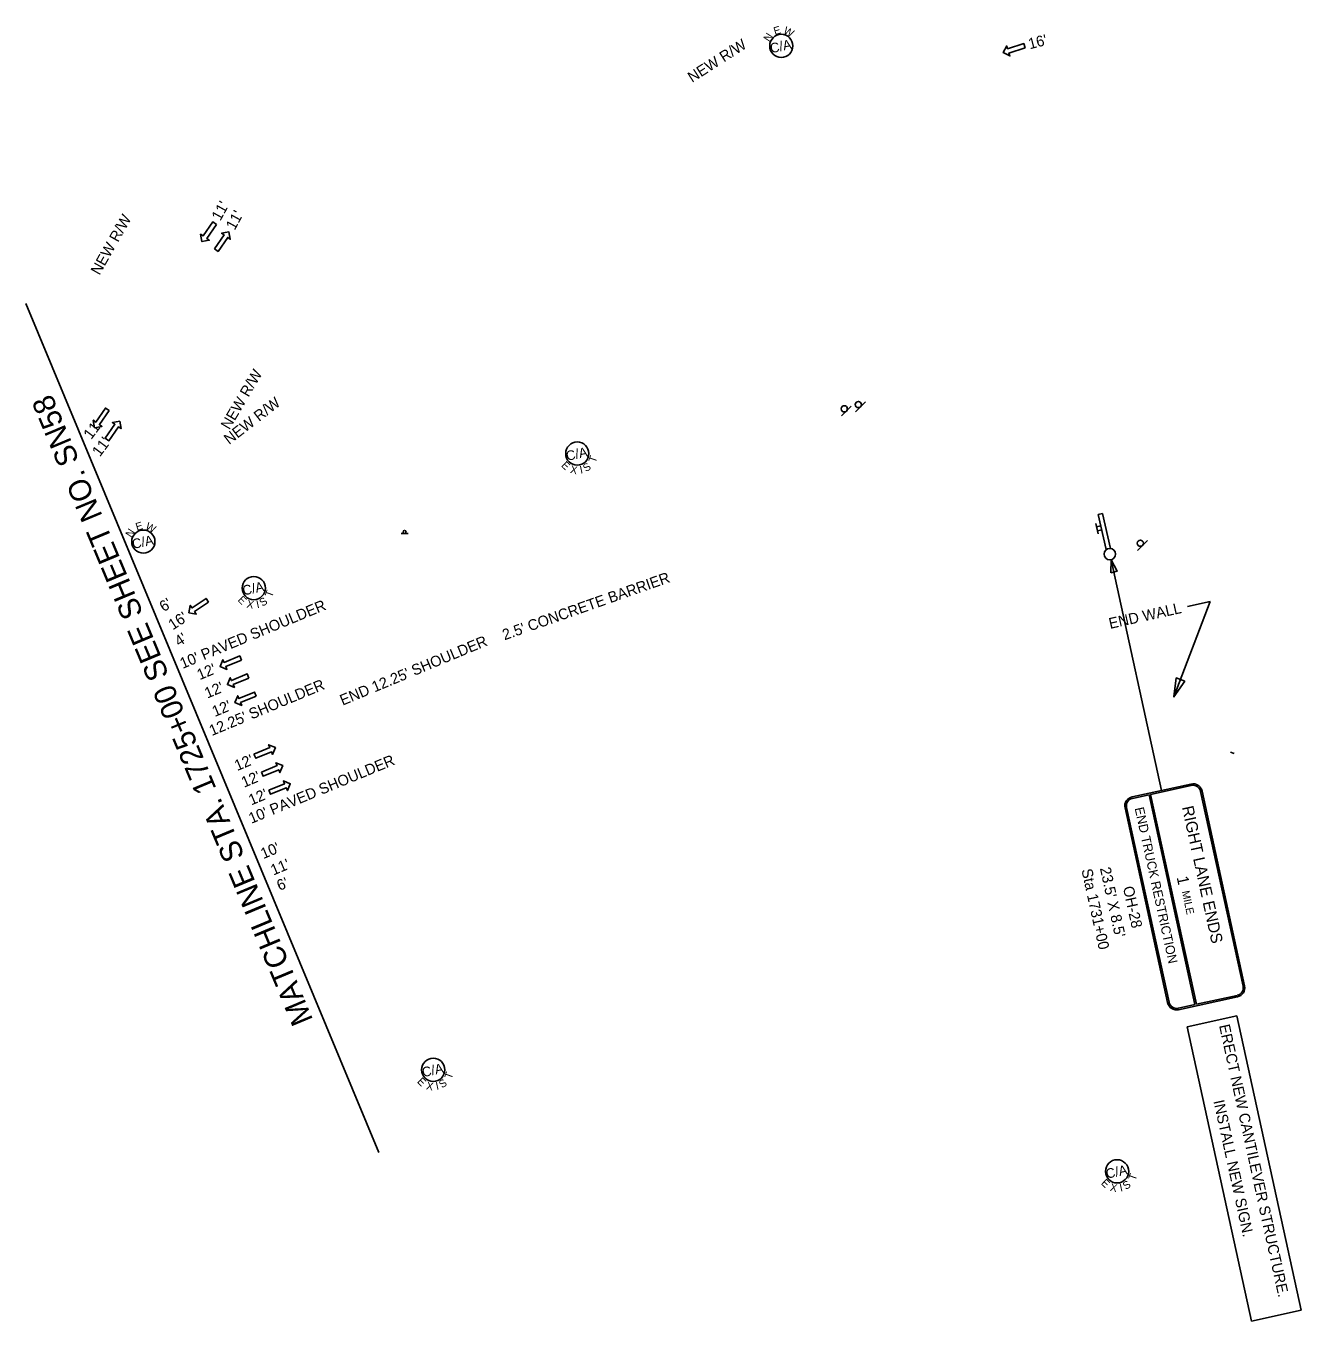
# Model space of a CAD drawing. Extents: x 1818895 to 1820505, y 1192175 to 1193276.
# Drawn here: x 1818895 to 1819720, y 1192175 to 1193013 of the extents above; entities that cross this region are included whole.
import ezdxf

# ---------------------------------------------------------------- set-up
doc = ezdxf.new("R2010")
doc.units = 0
for name, color, linetype in [('RD_PD_Final_LnLine', 7, 'Continuous'), ('RD_PD_Final_TX', 7, 'Continuous'), ('RD_PD_RW_TX', 7, 'Continuous'), ('RD_PD_WallFill', 7, 'Continuous'), ('RD_SHT_MatchLine', 7, 'Continuous'), ('RD_SHT_TX', 7, 'Continuous'), ('RD_Sketch10', 7, 'Continuous'), ('RD_Sketch8', 7, 'Continuous'), ('SN_P_Signs', 7, 'Continuous'), ('TERMINATOR', 7, 'Continuous')]:
    doc.layers.add(name, color=color, linetype=linetype)

# ---------------------------------------------------------------- blocks, each defined once
blk = doc.blocks.new('SARRW2')
at = {"layer": 'RD_PD_Final_LnLine'}
blk.add_lwpolyline([(-12, 1.2), (-12, -1.2), (-2.83, -1.2), (-2.83, -2.83), (0, 0), (-2.83, 2.83), (-2.83, 1.2)], close=True, dxfattribs=at)

msp = doc.modelspace()

# ---------------------------------------------------------------- linework, layer by layer
at = {"layer": 'RD_PD_Final_TX'}
for q in [(1819638.16, 1192578.62), (1819647.02, 1192637.18)]:
    msp.add_line((1819661.55, 1192640.41), q, dxfattribs=at)
at = {"layer": 'RD_PD_WallFill'}
msp.add_line((1819674.71, 1192542.96), (1819677.06, 1192542.1), dxfattribs=at)
at = {"layer": 'RD_SHT_MatchLine'}
msp.add_line((1818895.15, 1192833.24), (1819123.48, 1192283.8), dxfattribs=at)
at = {"layer": 'RD_Sketch10'}
for centre in [(1819384.05, 1192999.96), (1818971.16, 1192679.14)]:
    msp.add_circle(centre, 7.5, dxfattribs=at)
at = {"layer": 'RD_Sketch8'}
for centre in [(1819252, 1192736.14), (1819042.62, 1192649.07), (1819158.79, 1192337.31), (1819601.38, 1192271.61)]:
    msp.add_circle(centre, 7.5, dxfattribs=at)
at = {"layer": 'SN_P_Signs'}
for p, q in [((1819422.99, 1192760.46), (1819429.36, 1192766.82)), ((1819432.15, 1192763.21), (1819438.51, 1192769.57)), ((1819589.2, 1192684.12), (1819587.64, 1192690.9)), ((1819590.82, 1192689.4), (1819588.11, 1192688.77)), ((1819137.96, 1192684.34), (1819142.46, 1192684.34)), ((1819591.42, 1192686.79), (1819588.72, 1192686.16)), ((1819614.66, 1192673.49), (1819621.02, 1192679.85)), ((1819630.15, 1192518.11), (1819597.5, 1192667.45)), ((1819611.1, 1192513.95), (1819649.2, 1192522.28)), ((1819623.04, 1192515.54), (1819649.42, 1192521.3)), ((1819611.32, 1192512.97), (1819622.06, 1192515.32)), ((1819622.06, 1192515.32), (1819651.76, 1192379.53)), ((1819652.73, 1192379.74), (1819623.04, 1192515.54)), ((1819651.76, 1192379.53), (1819641.01, 1192377.18)), ((1819679.32, 1192384.53), (1819641.22, 1192376.2)), ((1819679.11, 1192385.51), (1819652.73, 1192379.74)), ((1819646.76, 1192365.19), (1819678.81, 1192372.2)), ((1819678.81, 1192372.2), (1819720.46, 1192181.7)), ((1819688.42, 1192174.69), (1819646.76, 1192365.19)), ((1819720.46, 1192181.7), (1819688.42, 1192174.69))]:
    msp.add_line(p, q, dxfattribs=at)
for points in [[(1819597.05, 1192674.77), (1819591.85, 1192697.31), (1819589.13, 1192696.69), (1819594.38, 1192673.97)], [(1819655.37, 1192517.49), (1819682.93, 1192391.46)], [(1819656.35, 1192517.7), (1819683.9, 1192391.68)], [(1819634.08, 1192380.78), (1819606.52, 1192506.81)], [(1819635.06, 1192381), (1819607.5, 1192507.02)]]:
    msp.add_lwpolyline(points, dxfattribs=at)
msp.add_lwpolyline([(1819597.39, 1192659.01), (1819597.54, 1192667.46), (1819601.38, 1192659.93)], close=True, dxfattribs=at)
for centre, radius in [((1819424.76, 1192765.08), 2), ((1819433.91, 1192767.83), 2), ((1819140.22, 1192685.35), 1), ((1819616.42, 1192678.12), 2), ((1819596.71, 1192671.08), 3.71)]:
    msp.add_circle(centre, radius, dxfattribs=at)
for centre, radius, start, end in [((1819650.49, 1192516.42), 6, 12.33377, 102.33377), ((1819650.49, 1192516.42), 5, 12.33377, 102.33377), ((1819612.39, 1192508.09), 6, 102.33377, 192.33377), ((1819612.39, 1192508.09), 5, 102.33377, 192.33377), ((1819678.04, 1192390.4), 5, 282.33377, 12.33377), ((1819678.04, 1192390.4), 6, 282.33377, 12.33377), ((1819639.94, 1192382.06), 6, 192.33377, 282.33377), ((1819639.94, 1192382.06), 5, 192.33377, 282.33377)]:
    msp.add_arc(centre, radius, start, end, dxfattribs=at)
at = {"layer": 'TERMINATOR'}
msp.add_lwpolyline([(1819645.22, 1192588.78), (1819638.16, 1192578.62), (1819639.61, 1192590.9)], close=True, dxfattribs=at)

# ---------------------------------------------------------------- block references
at = {"layer": 'RD_PD_Final_LnLine'}
for p, xscale, yscale, rotation in [((1819527.72, 1192995.67), 1.2000000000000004, 1.2000000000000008, -162.3629243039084), ((1819009.08, 1192873.36), 1.2000000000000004, 1.2000000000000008, -124.60867913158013), ((1819026.54, 1192879.58), 1.2000000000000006, 1.200000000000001, 55.39132086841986), ((1818939.64, 1192752.87), 1.2000000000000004, 1.2000000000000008, -124.60867913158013), ((1818955.84, 1192757.04), 1.2000000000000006, 1.200000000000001, 55.39132086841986), ((1819000.66, 1192633.16), 1.2000000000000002, 1.2000000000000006, -145.89054344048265), ((1819020.8, 1192598.3), 1.2000000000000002, 1.2000000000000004, -157.44760385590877), ((1819025.61, 1192586.62), 1.2000000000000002, 1.2000000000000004, -157.44760385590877), ((1819030.42, 1192574.95), 1.2000000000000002, 1.2000000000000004, -157.44760385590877), ((1819056.61, 1192545.82), 1.2000000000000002, 1.2000000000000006, 22.552396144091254), ((1819061.42, 1192534.15), 1.2000000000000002, 1.2000000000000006, 22.552396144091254), ((1819066.23, 1192522.47), 1.2000000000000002, 1.2000000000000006, 22.552396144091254)]:
    msp.add_blockref('SARRW2', p, dxfattribs=dict(at, xscale=xscale, yscale=yscale, rotation=rotation))

# ---------------------------------------------------------------- texts
at = {"layer": 'RD_PD_Final_TX'}
for s, rotation, p in [("16'", 14.40153, (1819544.86, 1192997.73)), ("11'", 61.26973, (1819020.99, 1192886.28)), ("11'", 61.26973, (1819030.26, 1192880.25)), ("11'", 53.1924, (1818937.44, 1192744.82)), ("11'", 53.1924, (1818943.04, 1192733.63)), ("2.5' CONCRETE BARRIER", 19.34104, (1819204.93, 1192615.25)), ("6'", 33.13596, (1818984.43, 1192633.43)), ("10' PAVED SHOULDER", 22.4268, (1818996.57, 1192596.73)), ('END WALL', 12.54893, (1819596.86, 1192622.62)), ("16'", 33.13596, (1818990.21, 1192621.66)), ("4'", 33.13596, (1818994.27, 1192610.99)), ("END 12.25' SHOULDER", 22.56659, (1819100.13, 1192572.94)), ("12'", 22.75903, (1819007.62, 1192589.42)), ("12'", 22.75903, (1819012.53, 1192577.52)), ("12.25' SHOULDER", 22.56659, (1819015.51, 1192553.29)), ("12'", 22.75903, (1819017.43, 1192565.62)), ("12'", 22.75903, (1819031.87, 1192530.6)), ("10' PAVED SHOULDER", 22.4268, (1819041.06, 1192496.47)), ("12'", 22.75903, (1819036.32, 1192519.82)), ("12'", 22.75903, (1819041.04, 1192508.37)), ("10'", 22.75903, (1819048.83, 1192473.63)), ("11'", 22.75903, (1819055.3, 1192463)), ("6'", 22.75903, (1819059.31, 1192453.05))]:
    msp.add_text(s, height=7, rotation=rotation, dxfattribs=at).set_placement(p)
at = {"layer": 'RD_PD_RW_TX'}
for rotation, p in [(32.70466, (1819326.34, 1192975.95)), (60.59761, (1818942.75, 1192851.15)), (59.61377, (1819026.85, 1192751.13)), (37.65796, (1819026.69, 1192741.63))]:
    msp.add_text('NEW R/W', height=7, rotation=rotation, dxfattribs=at).set_placement(p)
at = {"layer": 'RD_SHT_TX'}
msp.add_text('MATCHLINE STA. 1725+00 SEE SHEET NO. SN58', height=14.1726, rotation=112.67894, dxfattribs=at).set_placement((1819081.19, 1192369.63))
at = {"layer": 'RD_Sketch10'}
for s, height, rotation, p in [('N', 5, 57.1687, (1819376.28, 1193002.19)), ('E', 5, 16.63198, (1819379.91, 1193006.94)), ('W', 5, 331.60154, (1819384.92, 1193008.29)), ('C/A', 6.25, 12.29893, (1819377.51, 1192995.18)), ('N', 5, 57.1687, (1818963.38, 1192681.37)), ('E', 5, 16.63198, (1818967.01, 1192686.12)), ('W', 5, 331.60154, (1818972.02, 1192687.47)), ('C/A', 6.25, 12.29893, (1818964.61, 1192674.36))]:
    msp.add_text(s, height=height, rotation=rotation, dxfattribs=at).set_placement(p)
at = {"layer": 'RD_Sketch8'}
for s, height, rotation, p in [('C/A', 6.25, 12.29893, (1819245.46, 1192731.36)), ('E', 5, 315.51017, (1819241.24, 1192728.14)), ('S', 5, 34.09137, (1819257.71, 1192724)), ('T', 5, 70.48408, (1819263.81, 1192729.8)), ('X', 5, 347.93955, (1819247.11, 1192723.63)), ('I', 5, 12.09955, (1819254.18, 1192723.05)), ('C/A', 6.25, 12.29893, (1819036.08, 1192644.29)), ('T', 5, 70.48408, (1819054.43, 1192642.73)), ('E', 5, 315.51017, (1819031.86, 1192641.07)), ('X', 5, 347.93955, (1819037.73, 1192636.57)), ('I', 5, 12.09955, (1819044.8, 1192635.99)), ('S', 5, 34.09137, (1819048.33, 1192636.93)), ('C/A', 6.25, 12.29893, (1819152.25, 1192332.53)), ('T', 5, 70.48408, (1819170.6, 1192330.98)), ('E', 5, 315.51017, (1819148.03, 1192329.32)), ('X', 5, 347.93955, (1819153.9, 1192324.81)), ('I', 5, 12.09955, (1819160.97, 1192324.23)), ('S', 5, 34.09137, (1819164.5, 1192325.18)), ('C/A', 6.25, 12.29893, (1819594.83, 1192266.82)), ('T', 5, 70.48408, (1819613.19, 1192265.27)), ('E', 5, 315.51017, (1819590.61, 1192263.61)), ('X', 5, 347.93955, (1819596.49, 1192259.1)), ('I', 5, 12.09955, (1819603.55, 1192258.52)), ('S', 5, 34.09137, (1819607.08, 1192259.47))]:
    msp.add_text(s, height=height, rotation=rotation, dxfattribs=at).set_placement(p)
at = {"layer": 'SN_P_Signs'}
for s, height, rotation, p in [('END TRUCK RESTRICTION', 6, 282.33377, (1819612.71, 1192506.61)), ('RIGHT LANE ENDS', 7.5, 282.33377, (1819643.27, 1192507.28)), ('Sta 1731+00', 7, 282.33385, (1819578.27, 1192466.71)), ("23.5' X 8.5'", 7, 282.33385, (1819590.22, 1192467.74)), ('1', 7.5, 282.33377, (1819639.89, 1192461.88)), ('OH-28', 7, 282.33385, (1819605.11, 1192455.37)), ('MILE', 5, 282.33377, (1819643.18, 1192452.69)), ('ERECT NEW CANTILEVER STRUCTURE.', 7, 282.33385, (1819667.33, 1192365.97)), ('INSTALL NEW SIGN.', 7, 282.33385, (1819663.69, 1192317.05))]:
    msp.add_text(s, height=height, rotation=rotation, dxfattribs=at).set_placement(p)

doc.saveas('drawing.dxf')
